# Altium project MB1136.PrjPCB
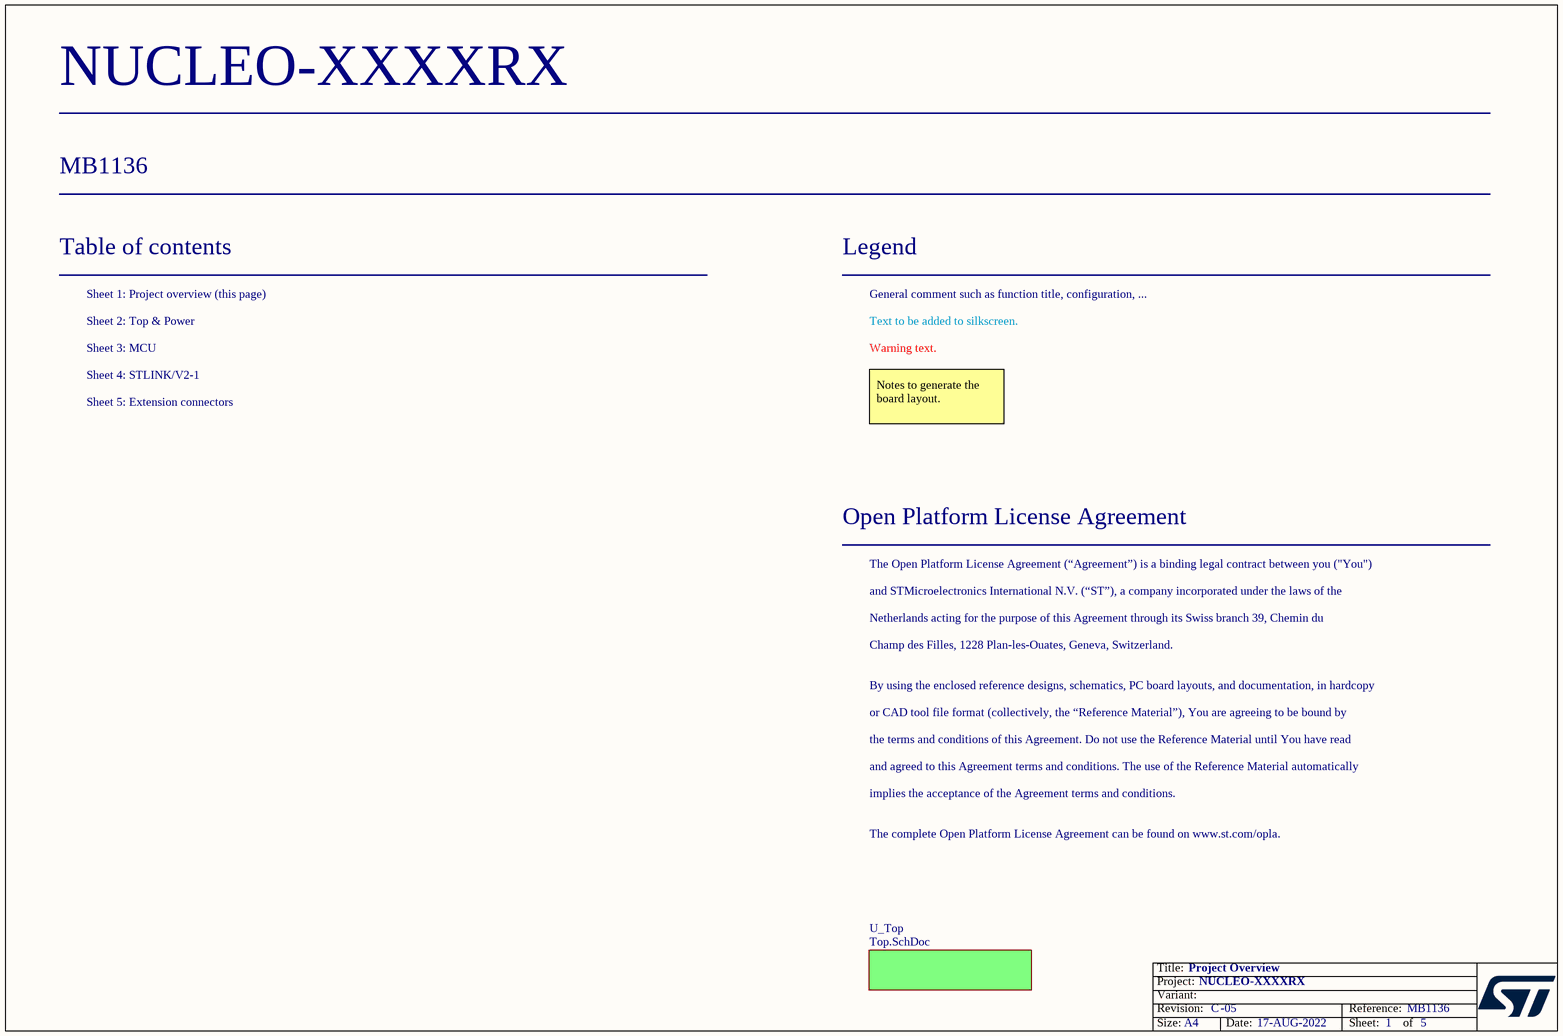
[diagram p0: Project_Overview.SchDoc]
Board_Reference: MB1136; Board_PCB_revision: C; Board_name: NUCLEO-XXXXRX; Board_Document_Date: 17-AUG-2022; Board_Assembly_revision: 05
5 sheets, 172 parts. Net scope: flat (ports and power ports of the same name join across sheets).
Sheets:
  Project_Overview.SchDoc
    U_Top = Top.SchDoc
      U_ST_LINK_V2-1 = ST_LINK_V2-1.SCHDOC
      U_Connectors = Connectors.SchDoc
      U_MCU_64 = MCU_64.SchDoc

## Sheet Project_Overview.SchDoc: Project Overview
size A4; Date: Not used; ApprovedBy: Not used; CheckedBy: Not used; Author: Not used; CompanyName: STMicroelectronics; DrawnBy: Not used; Engineer: Not used; Organization: Not used; Address1: Not used; Address2: Not used; Address3: Not used; Address4: Not used; DocumentNumber: MB1136; Revision: Not used; SheetNumber: 1; SheetTotal: 5

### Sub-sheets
U_Top = Top.SchDoc: no entries

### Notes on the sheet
- Table of contents
- Sheet 1: Project overview (this page)
- Legend
- General comment such as function title, configuration, ...
- Sheet 2: Top & Power
- Sheet 3: MCU
- Sheet 4: STLINK/V2-1
- Text to be added to silkscreen.
- Warning text.
- Sheet 5: Extension connectors
- Notes to generate the board layout.
- Open Platform License Agreement
- The Open Platform License Agreement (“Agreement”) is a binding legal contract between you ("You")
- and STMicroelectronics International N.V. (“ST”), a company incorporated under the laws of the
- Netherlands acting for the purpose of this Agreement through its Swiss branch 39, Chemin du
- Champ des Filles, 1228 Plan-les-Ouates, Geneva, Switzerland.
- By using the enclosed reference designs, schematics, PC board layouts, and documentation, in hardcopy
- or CAD tool file format (collectively, the “Reference Material”), You are agreeing to be bound by
- the terms and conditions of this Agreement. Do not use the Reference Material until You have read
- and agreed to this Agreement terms and conditions. The use of the Reference Material automatically
- implies the acceptance of the Agreement terms and conditions.
- The complete Open Platform License Agreement can be found on www.st.com/opla.

## Sheet Top.SchDoc: TOP & POWER
size A4; DocumentNumber: MB1136; Revision: C.3; SheetNumber: 2; SheetTotal: 5; Project: NUCLEO-XXXXRX
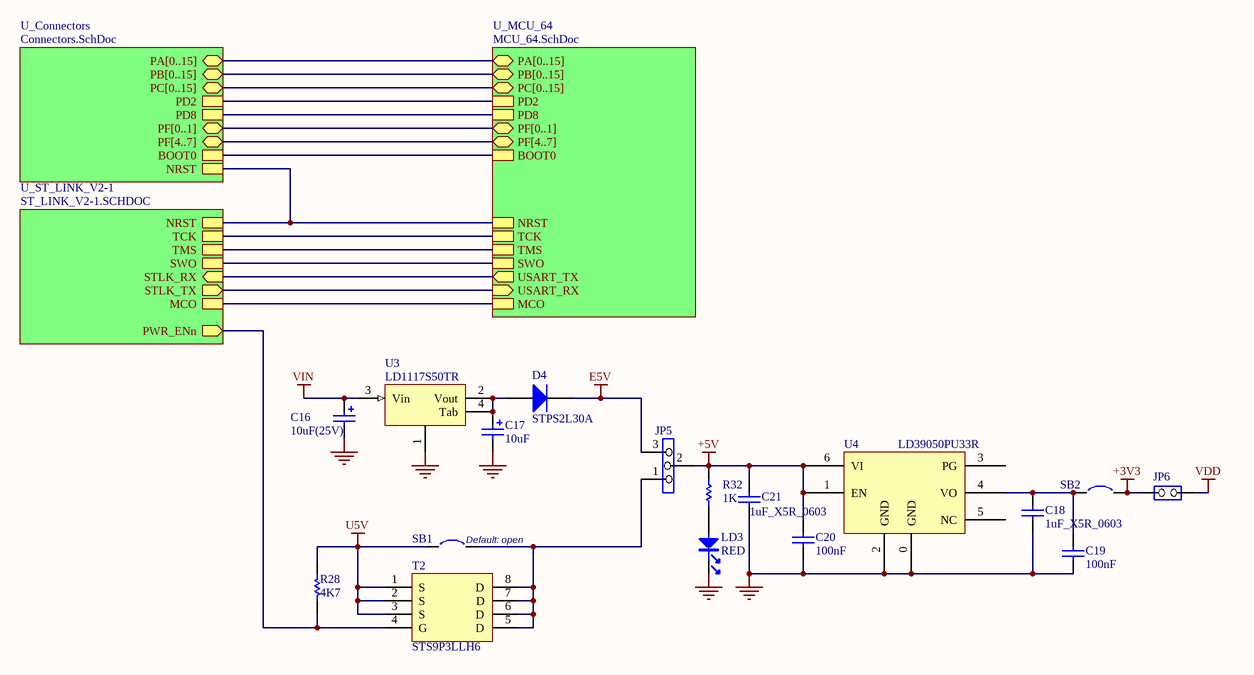
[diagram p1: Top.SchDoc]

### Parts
C16  10uF(25V)  [TAN-B]
C17  10uF  [TAN-A]
C18  1uF_X5R_0603  [0603C]
C19  100nF  [0603C]
C20  100nF  [0603C]
C21  1uF_X5R_0603  [0603C]
D4  STPS2L30A  [SMA]
JP5  (no value)  [SIP3]
JP6  (no value)  [SIP2/2.54]
LD3  RED  [0603D]
R28  4K7  [0603R]
R32  1K  [0603R]
SB1  Circuit Breaker  [JP2_SMD]  (value not drawn)
SB2  Circuit Breaker  [JP2_SMD]  (value not drawn)
T2  value STS9P3LLH6  [ICC_SO8_5X4_P127]  (hidden comment: TRANS_P-CHANNEL_STS9P3LLH6)
U3  LD1117S50TR  [SOT-223]
U4  LD39050PU33R  [DFN6(3X3)]

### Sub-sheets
U_Connectors = Connectors.SchDoc: PA[0..15] (bidir), PB[0..15] (bidir), PC[0..15] (bidir), PF[4..7] (bidir), PD2, PD8, PF[0..1] (bidir), NRST, BOOT0
U_MCU_64 = MCU_64.SchDoc: NRST, MCO, USART_RX (in), USART_TX (out), PA[0..15] (bidir), PB[0..15] (bidir), PC[0..15] (bidir), PF[4..7] (bidir), PD2, TCK, TMS, SWO, PD8, PF[0..1] (bidir), BOOT0
U_ST_LINK_V2-1 = ST_LINK_V2-1.SCHDOC: TMS, TCK, MCO, NRST, STLK_RX (in), STLK_TX (out), SWO, PWR_ENn (out)

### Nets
+3V3: JP6.1(COMMON) SB2.2
+5V: C20.2 C21.1 JP5.2 R32.2 U4.1(EN) U4.6(VI)
E5V: D4.2(K) JP5.3
GND: C16.2 C17.2 C18.2 C19.1 C20.1 C21.2 LD3.2 U3.1 U4.0(GND) U4.2(GND)
U5V: R28.1 SB1.1 T2.1(S) T2.2(S) T2.3(S)
VDD: JP6.2(NO)
VIN: C16.1 U3.3(Vin)
NetC17_1: C17.1 D4.1(A) U3.2(Vout) U3.4(Tab)
NetC18_1: C18.1 C19.2 SB2.1 U4.4(VO)
NetJP5_1: JP5.1 SB1.2 T2.5(D) T2.6(D) T2.7(D) T2.8(D)
NetLD3_1: LD3.1 R32.1
NetR28_2: R28.2 T2.4(G) ; sheet U_ST_LINK_V2-1/PWR_ENn
(unnamed): sheet U_ST_LINK_V2-1/TMS, sheet U_MCU_64/TMS
(unnamed): sheet U_ST_LINK_V2-1/TCK, sheet U_MCU_64/TCK  [a separate net that carries the same name]
(unnamed): sheet U_ST_LINK_V2-1/MCO, sheet U_MCU_64/MCO  [a separate net that carries the same name]
(unnamed): sheet U_ST_LINK_V2-1/NRST, sheet U_Connectors/NRST, sheet U_MCU_64/NRST  [a separate net that carries the same name]
(unnamed): sheet U_ST_LINK_V2-1/STLK_RX, sheet U_MCU_64/USART_TX  [a separate net that carries the same name]
(unnamed): sheet U_ST_LINK_V2-1/STLK_TX, sheet U_MCU_64/USART_RX  [a separate net that carries the same name]
(unnamed): sheet U_ST_LINK_V2-1/SWO, sheet U_MCU_64/SWO  [a separate net that carries the same name]
(unnamed): sheet U_Connectors/PD2, sheet U_MCU_64/PD2  [a separate net that carries the same name]
(unnamed): sheet U_Connectors/PD8, sheet U_MCU_64/PD8  [a separate net that carries the same name]
(unnamed): sheet U_Connectors/BOOT0, sheet U_MCU_64/BOOT0  [a separate net that carries the same name]

Not connected (* = marked no-connect by the designer): U4 3(PG) 5(NC)

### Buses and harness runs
bus sheet U_Connectors/PA[0..15] = sheet U_MCU_64/PA[0..15]
bus sheet U_Connectors/PB[0..15] = sheet U_MCU_64/PB[0..15]
bus sheet U_Connectors/PC[0..15] = sheet U_MCU_64/PC[0..15]
bus sheet U_Connectors/PF[0..1] = sheet U_MCU_64/PF[0..1]
bus sheet U_Connectors/PF[4..7] = sheet U_MCU_64/PF[4..7]

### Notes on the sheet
- (near SB1) Default: open

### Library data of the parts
C16 C17 = Cap Pol1: Polarized Capacitor (Radial)
C18 C21 = CAP SMD 0603  X5R 1µF 25V 10%: 0603  X5R 1µF; Rated voltage: 25V; Tolerance: 10%
C19 C20 = Capacitor_ST: Capacitor 0402 / 0603 / 0805
D4 = STPS2L30A: Manuf_1: STM; Provided: ST; Order: BAT60JFILM; ECCN_US/EU: EAR99/NEC
JP5 = Jumper3
JP6 = JP2
LD3 = PHOTO
R28 = Res1: Resistor; Value: 1K
R32 = Resistor_ST: Resistor 0402 / 0603 / 0805; Value: 10K
SB1 SB2 = Circuit Breaker: Solder: NO
T2 = MCD-02507: Transistor, MOSFET, P-CH, -30V, -9A, SO-8; Part_Preference: Recommended; Manufacturer: STMICROELECTRONICS; Component_Country_Of_Origin: China; ShowFields: YES; ID: 4613
U3 = LD1117
U4 = LD39050P

## Sheet ST_LINK_V2-1.SCHDOC: STLINK/V2-1
size A4; DocumentNumber: MB1136; Revision: C.3; SheetNumber: 4; SheetTotal: 5; Project: NUCLEO-XXXXRX
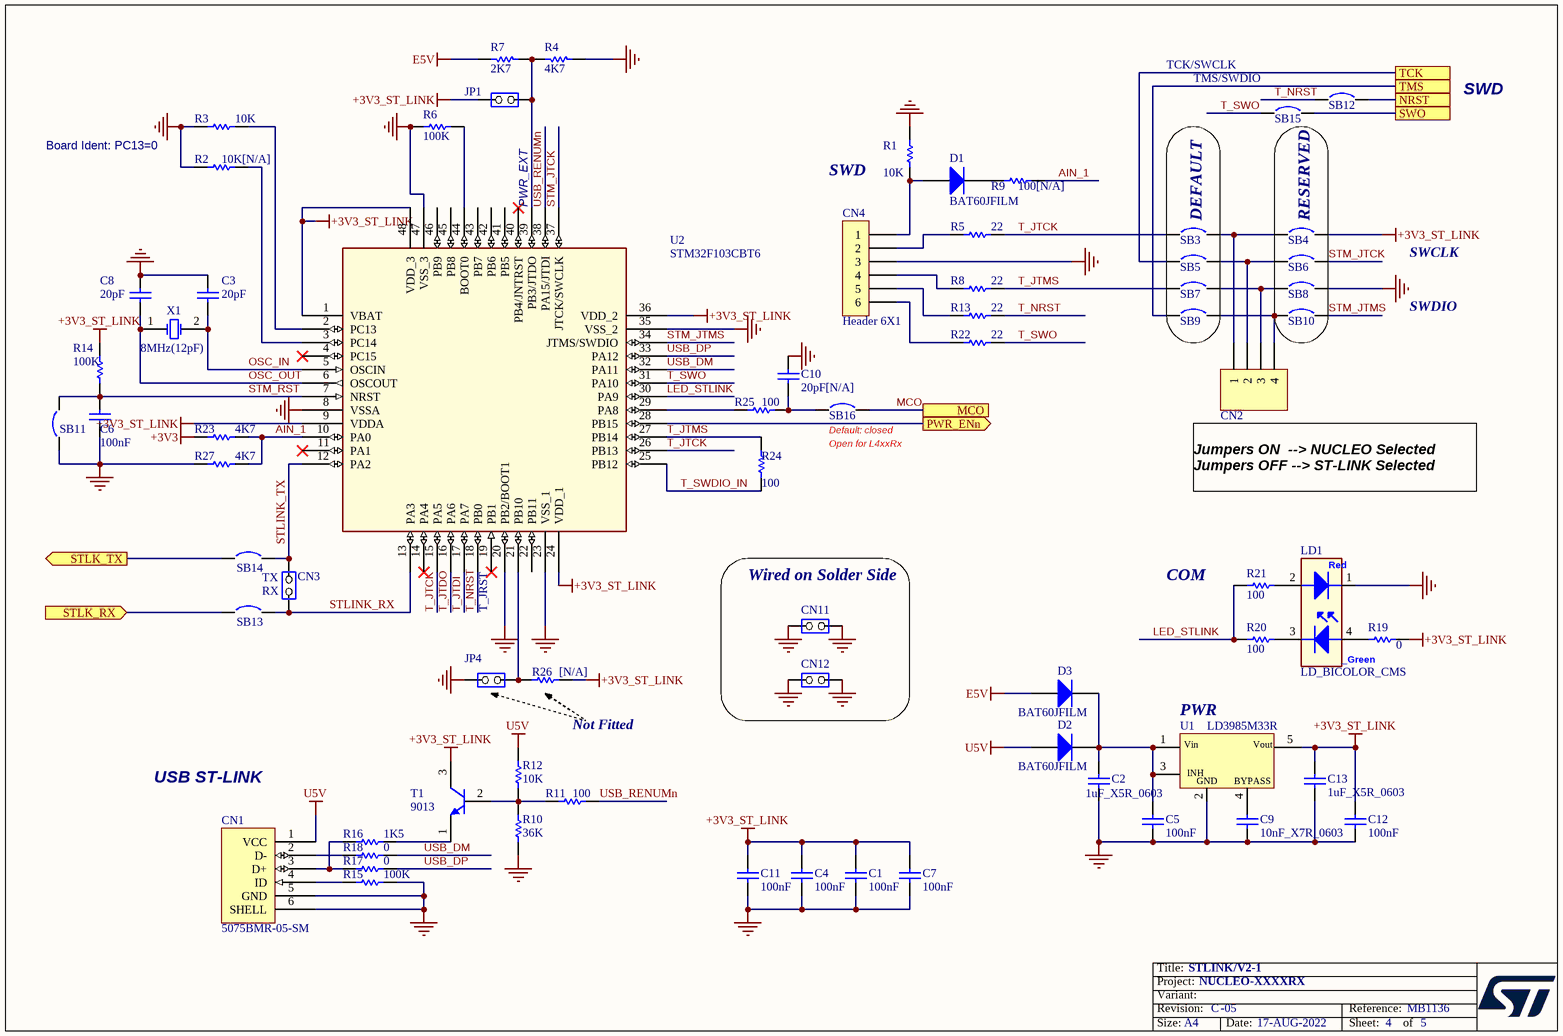
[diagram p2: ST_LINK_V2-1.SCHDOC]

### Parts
C1  100nF  [0603C]
C2  1uF_X5R_0603  [0603C]
C3  20pF  [0603C]
C4  100nF  [0603C]
C5  100nF  [0603C]
C6  100nF  [0603C]
C7  100nF  [0603C]
C8  20pF  [0603C]
C9  10nF_X7R_0603  [0603C]
C10  20pF[N/A]  [0603C]
C11  100nF  [0603C]
C12  100nF  [0603C]
C13  1uF_X5R_0603  [0603C]
CN1  5075BMR-05-SM  [USB-MINI-B-SMD]
CN2  Header 4  [1*4]  (value not drawn)
CN3  (no value)  [SIP2/2.54]
CN4  Header 6X1  [1*6P]
CN11  (no value)  [SIP2/2.54]
CN12  (no value)  [SIP2/2.54]
D1  BAT60JFILM  [SOD323/A]
D2  BAT60JFILM  [SOD323/A]
D3  BAT60JFILM  [SOD323/A]
JP1  (no value)  [SIP2/2.54]
JP4  (no value)  [SIP2/2.54]
LD1  LD_BICOLOR_CMS  [HSMF-A201]
R1  10K  [0603R]
R2  10K[N/A]  [0603R]
R3  10K  [0603R]
R4  4K7  [0603R]
R5  22  [0603R]
R6  100K  [0603R]
R7  2K7  [0603R]
R8  22  [0603R]
R9  100[N/A]  [0603R]
R10  36K  [0603R]
R11  100  [0603R]
R12  10K  [0603R]
R13  22  [0603R]
R14  100K  [0603R]
R15  100K  [0603R]
R16  1K5  [0603R]
R17  0  [0603R]
R18  0  [0603R]
R19  0  [0603R]
R20  100  [0603R]
R21  100  [0603R]
R22  22  [0603R]
R23  4K7  [0603R]
R24  100  [0603R]
R25  100  [0603R]
R26  [N/A]  [0603R]
R27  4K7  [0603R]
SB3  Circuit Breaker  [JP2_SMD]  (value not drawn)
SB4  Circuit Breaker  [JP2_SMD]  (value not drawn)
SB5  Circuit Breaker  [JP2_SMD]  (value not drawn)
SB6  Circuit Breaker  [JP2_SMD]  (value not drawn)
SB7  Circuit Breaker  [JP2_SMD]  (value not drawn)
SB8  Circuit Breaker  [JP2_SMD]  (value not drawn)
SB9  Circuit Breaker  [JP2_SMD]  (value not drawn)
SB10  Circuit Breaker  [JP2_SMD]  (value not drawn)
SB11  Circuit Breaker  [JP2_SMD]  (value not drawn)
SB12  Circuit Breaker  [JP2_SMD]  (value not drawn)
SB13  Circuit Breaker  [JP2_SMD]  (value not drawn)
SB14  Circuit Breaker  [JP2_SMD]  (value not drawn)
SB15  Circuit Breaker  [JP2_SMD]  (value not drawn)
SB16  Circuit Breaker  [JP2_SMD]  (value not drawn)
T1  9013  [SOT-23]
U1  LD3985M33R  [SOT-23-5L]
U2  STM32F103CBT6  [QFP48 7X7]
X1  8MHz(12pF)  [XTAL1]

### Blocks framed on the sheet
DEFAULT: SB3 SB5 SB7 SB9
RESERVED: SB4 SB6 SB8 SB10
Wired on Solder Side: CN11 CN12

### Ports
MCO, NRST, PWR_ENn (out), STLK_RX (in), STLK_TX (out), SWO, TCK, TMS

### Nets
+3V3: R23.1
+3V3_ST_LINK: C1.2 C4.2 C7.2 C11.2 C12.2 C13.1 JP1.1(COMMON) R14.2 R19.2 R26.1 SB4.2 T1.3(C) U1.5(Vout) U2.1(VBAT) U2.9(VDDA) U2.24(VDD_1) U2.36(VDD_2) U2.48(VDD_3)
E5V: D3.1(A) R7.1
GND: C1.1 C2.1 C3.2 C4.1 C5.1 C6.1 C7.1 C8.2 C9.1 C10.2 C11.1 C12.1 C13.2 CN1.5(GND) CN1.6(SHELL) CN4.3 CN11.1(COMMON) CN11.2(NO) CN12.1(COMMON) CN12.2(NO) JP4.1(COMMON) LD1.1 R1.2 R2.1 R3.1 R4.2 R6.1 R10.1 R15.2 R27.1 SB8.2 SB11.1 U1.2(GND) U2.8(VSSA) U2.20(PB2/BOOT1) U2.23(VSS_1) U2.35(VSS_2) U2.47(VSS_3)
U5V: CN1.1(VCC) D2.1(A) R12.2
AIN_1: R9.2 R23.2 R27.2 U2.10(PA0)
LED_STLINK: R20.1 R21.1 U2.30(PA9)
MCO: SB16.2 ; port MCO
NRST: SB12.2 ; port NRST
OSC_IN: C3.1 U2.5(OSCIN) X1.2(OSC2)
OSC_OUT: C8.1 U2.6(OSCOUT) X1.1(OSC1)
PA13: SB9.1 ; port TMS
PA14: SB5.1 ; port TCK
PB3: SB15.2 ; port SWO
STLINK_RX: CN3.1(COMMON) SB13.2 U2.13(PA3)
STLINK_TX: CN3.2(NO) SB14.2 U2.12(PA2)
STM_JTCK: SB6.2 U2.37(JTCK/SWCLK)
STM_JTMS: SB10.2 U2.34(JTMS/SWDIO)
STM_RST: C6.2 R14.1 SB11.2 U2.7(NRST)
T_JTCK: R5.2 SB3.1 U2.15(PA5) U2.26(PB13)
T_JTDI: U2.17(PA7)
T_JTDO: U2.16(PA6)
T_JTMS: R8.2 R24.2 SB7.1 U2.27(PB14)
T_NRST: R13.2 SB12.1 U2.18(PB0)
T_SWDIO_IN: R24.1 U2.25(PB12)
T_SWO: R22.2 SB15.1 U2.31(PA10)
USB_DM: R18.2 U2.32(PA11)
USB_DP: R17.2 U2.33(PA12)
USB_RENUMn: R11.2 U2.38(PA15/JTDI)
NetC2_2: C2.2 C5.2 D2.2(K) D3.2(K) U1.1(Vin) U1.3(CE)
NetC9_2: C9.2 U1.4(BYPASS)
NetC10_1: C10.1 R25.2 SB16.1
NetCN1_2: CN1.2(D-) R18.1
NetCN1_3: CN1.3(D+) R16.1 R17.1
NetCN1_4: CN1.4(ID) R15.1
NetCN2_1: CN2.1 SB3.2 SB4.1
NetCN2_2: CN2.2 SB5.2 SB6.1
NetCN2_3: CN2.3 SB7.2 SB8.1
NetCN2_4: CN2.4 SB9.2 SB10.1
NetCN4_1: CN4.1 D1.1(A) R1.1
NetCN4_2: CN4.2 R5.1
NetCN4_4: CN4.4 R8.1
NetCN4_5: CN4.5 R13.1
NetCN4_6: CN4.6 R22.1
NetD1_2: D1.2(K) R9.1
NetJP1_2: JP1.2(NO) R4.1 R7.2 U2.39(PB3/JTDO)
NetJP4_2: JP4.2(NO) R26.2 U2.21(PB10)
NetLD1_2: LD1.2 R21.2
NetLD1_3: LD1.3 R20.2
NetLD1_4: LD1.4 R19.1
NetR2_2: R2.2 U2.3(PC14)
NetR3_2: R3.2 U2.2(PC13)
NetR6_2: R6.2 U2.44(BOOT0)
NetR10_2: R10.2 R11.1 R12.1 T1.2(B)
NetR16_2: R16.2 T1.1(E)
NetR25_1: R25.1 U2.29(PA8)
NetSB13_1: SB13.1 ; port STLK_RX
NetSB14_1: SB14.1 ; port STLK_TX
NetU2_28: U2.28(PB15) ; port PWR_ENn

Not connected (* = marked no-connect by the designer): U2 4(PC15)* 11(PA1)* 14(PA4)* 19(PB1)* 22(PB11) 40(PB4/JNTRST)* 41(PB5) 42(PB6) 43(PB7) 45(PB8) 46(PB9)

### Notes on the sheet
- TCK/SWCLK
- (near SB15) TMS/SWDIO
- SWD
- Board Ident: PC13=0
- (near U2) PWR_EXT
- SWCLK
- SWDIO
- (near SB16) Default: closed
- (near SB16) Open for L4xxRx
- Jumpers ON  --> NUCLEO Selected
  Jumpers OFF --> ST-LINK Selected
- TX
- COM
- RX
- T_JRST
- (near U1) PWR
- USB ST-LINK
- Not Fitted

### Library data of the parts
C1 C4-C7 C11 C12 = Capacitor_ST: Capacitor 0402 / 0603 / 0805
C2 C13 = CAP SMD 0603  X5R 1µF 25V 10%: as C18 on sheet Top
C3 C8 C10 = Capacitor_ST: Capacitor 0402 / 0603 / 0805; Value: 100nF
C9 = CAP SMD 0603  X7R 10000PF 50V 10%: 0603  X7R 10NF; Order code RS: 2040779; Rated voltage: 50V; Tolerance: 10%
CN1 = USB-MINI-typeB connector
CN2 = Header 4: Header, 4-Pin, Single row
CN3 = JP2: Fitted: NO
CN4 = Header 6X1: Header, 6-Pin, Single row
CN11 CN12 JP1 JP4 = JP2
D1-D3 = BAT60JFILM: Manuf_1: STM; Provided: ST; ECCN_US/EU: EAR99/NEC
LD1 = LD_BICOLOR_CMS: Bicolor Led; Manuf_Part_1: HSMF-A201-A00J1; Manuf_1: Avago Technologies; Ref St: xxxxxx; cap_dec: ----
R1 R3 = Resistor_ST: Resistor 0402 / 0603 / 0805
R2 R23 R27 = Resistor_ST: Resistor 0402 / 0603 / 0805; Value: 10K; Fitted: NO
R4 R7 R10 R12 R26 = Res1: Resistor; Value: 1K
R5 R6 R8 R9 R11 R13-R22 R24 R25 = Resistor_ST: Resistor 0402 / 0603 / 0805; Value: 10K
SB3 SB5 SB7 SB9 SB11 SB13-SB16 = Circuit Breaker: Solder: NO
SB4 SB6 SB8 SB10 SB12 = Circuit Breaker: Solder: YES
T1 = NPN: NPN Bipolar Transistor; Code - JEDEC: TO-226-AA
U1 = LD3985M33R: Ultra low drop-low noise BiCMOS voltage, regulators low ESR capacitors compatible; Manuf_1: STM; Provided: ST; Ref St: 9176161; ECCN_US/EU: EAR99/NEC
U2 = STM32F103CBT6: Medium-density performance line ARM-based 32-bit MCU with 64KB Flash; Manuf_Part_1: STM32F103C8T6; Manuf_1: STM; Ref St: 9175981; Provided: ST; ECCN_US/EU: 3A991A2/NEC
X1 = XTAL: Crystal Oscillator

## Sheet Connectors.SchDoc: Extension connectors
size A4; DocumentNumber: MB1136; Revision: C.3; SheetNumber: 5; SheetTotal: 5; Project: NUCLEO-XXXXRX
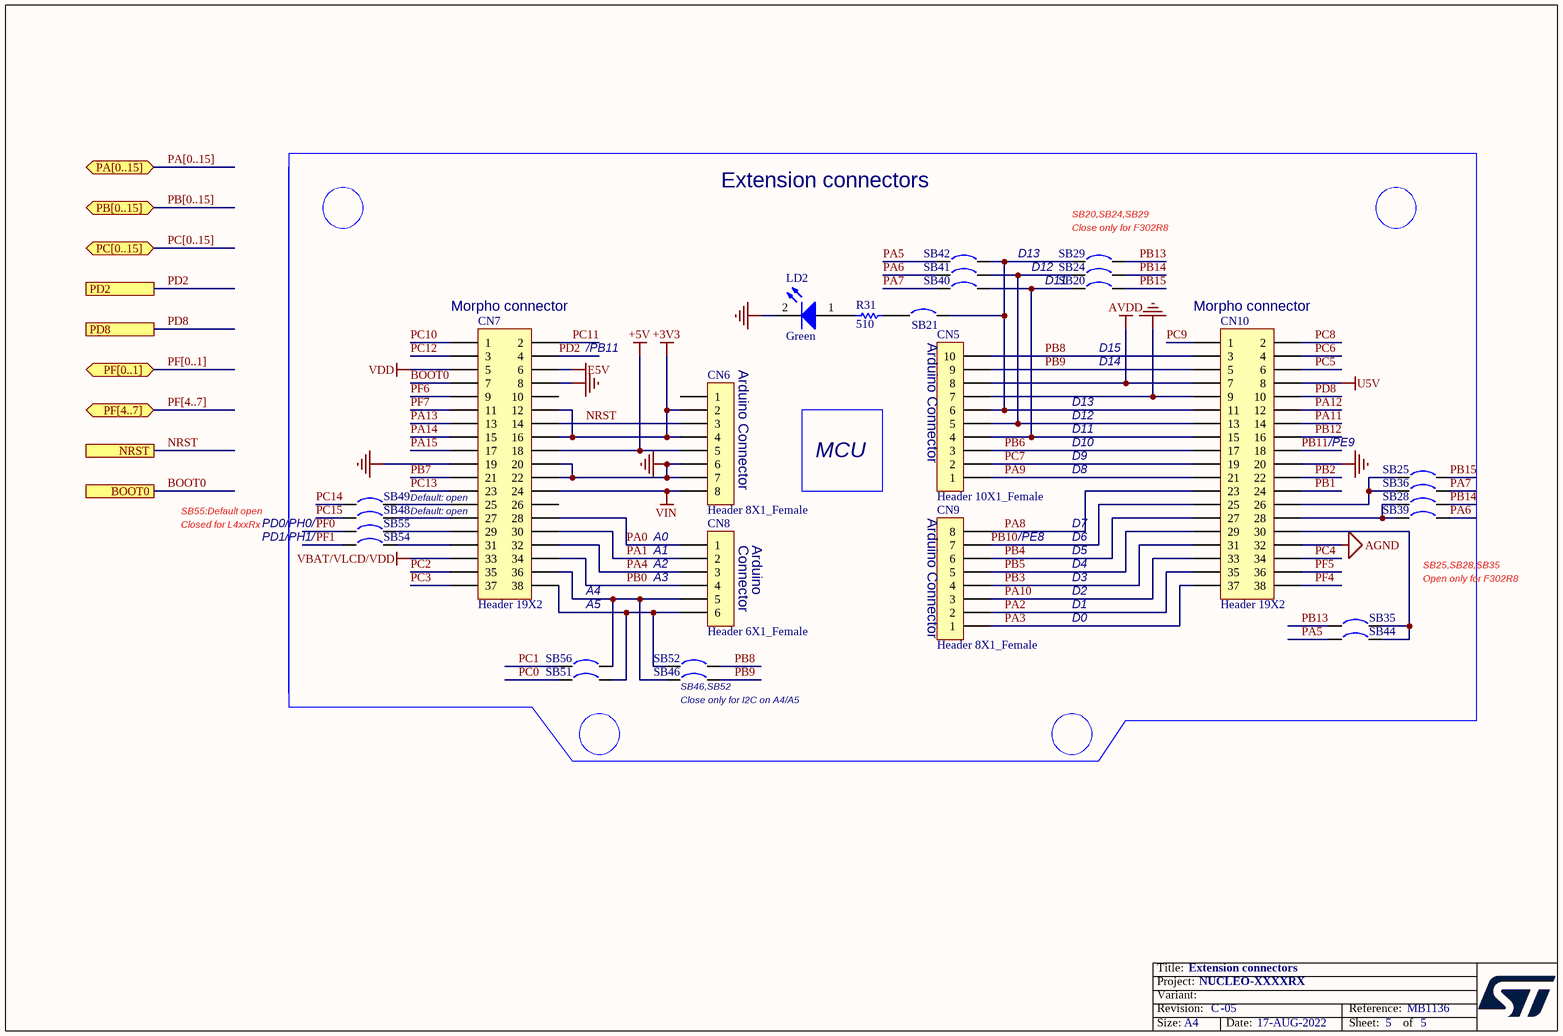
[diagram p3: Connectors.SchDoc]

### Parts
CN5  Header 10X1_Female  [1*10P_FEMALE]
CN6  Header 8X1_Female  [1*8P_FEMALE]
CN7  Header 19X2  [2*19P]
CN8  Header 6X1_Female  [1*6P_FEMALE]
CN9  Header 8X1_Female  [1*8P_FEMALE]
CN10  Header 19X2  [2*19P]
LD2  Green  [0603D]
R31  510  [0603R]
SB20  Circuit Breaker  [JP2_SMD]  (value not drawn)
SB21  Circuit Breaker  [JP2_SMD]  (value not drawn)
SB24  Circuit Breaker  [JP2_SMD]  (value not drawn)
SB25  Circuit Breaker  [JP2_SMD]  (value not drawn)
SB28  Circuit Breaker  [JP2_SMD]  (value not drawn)
SB29  Circuit Breaker  [JP2_SMD]  (value not drawn)
SB35  Circuit Breaker  [JP2_SMD]  (value not drawn)
SB36  Circuit Breaker  [JP2_SMD]  (value not drawn)
SB39  Circuit Breaker  [JP2_SMD]  (value not drawn)
SB40  Circuit Breaker  [JP2_SMD]  (value not drawn)
SB41  Circuit Breaker  [JP2_SMD]  (value not drawn)
SB42  Circuit Breaker  [JP2_SMD]  (value not drawn)
SB44  Circuit Breaker  [JP2_SMD]  (value not drawn)
SB46  Circuit Breaker  [JP2_SMD]  (value not drawn)
SB48  Circuit Breaker  [JP2_SMD]  (value not drawn)
SB49  Circuit Breaker  [JP2_SMD]  (value not drawn)
SB51  Circuit Breaker  [JP2_SMD]  (value not drawn)
SB52  Circuit Breaker  [JP2_SMD]  (value not drawn)
SB54  Circuit Breaker  [JP2_SMD]  (value not drawn)
SB55  Circuit Breaker  [JP2_SMD]  (value not drawn)
SB56  Circuit Breaker  [JP2_SMD]  (value not drawn)

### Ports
BOOT0, NRST, PA[0..15] (bidir), PB[0..15] (bidir), PC[0..15] (bidir), PD2, PD8, PF[0..1] (bidir), PF[4..7] (bidir)

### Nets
+3V3: CN6.2 CN6.4 CN7.12 CN7.16
+5V: CN6.5 CN7.18
AGND: CN10.32
AVDD: CN5.8 CN10.7
E5V: CN7.6
GND: CN5.7 CN6.6 CN6.7 CN7.8 CN7.19 CN7.20 CN7.22 CN10.9 CN10.20 LD2.2(K)
U5V: CN10.8
VBAT/VLCD/VDD: CN7.33
VDD: CN7.5
VIN: CN6.8 CN7.24
BOOT0: CN7.7 ; port BOOT0
NRST: CN6.3 CN7.14 ; port NRST
PA0: CN7.28 CN8.1
PA1: CN7.30 CN8.2
PA2: CN9.2 CN10.35
PA3: CN9.1 CN10.37
PA4: CN7.32 CN8.3
PA5: SB42.1 SB44.2
PA6: SB39.1 SB41.1
PA7: SB36.1 SB40.1
PA8: CN9.8 CN10.23
PA9: CN5.1 CN10.21
PA10: CN9.3 CN10.33
PA11: CN10.14
PA12: CN10.12
PA13: CN7.13
PA14: CN7.15
PA15: CN7.17
PB0: CN7.34 CN8.4
PB1: CN10.24
PB2: CN10.22
PB3: CN9.4 CN10.31
PB4: CN9.6 CN10.27
PB5: CN9.5 CN10.29
PB6: CN5.3 CN10.17
PB7: CN7.21
PB8: CN5.10 CN10.3 SB52.2
PB9: CN5.9 CN10.5 SB46.2
PB10: CN9.7 CN10.25
PB11: CN10.18
PB12: CN10.16
PB13: SB29.2 SB35.2
PB14: SB24.2 SB28.1
PB15: SB20.2 SB25.1
PC0: SB51.1
PC1: SB56.1
PC2: CN7.35
PC3: CN7.37
PC4: CN10.34
PC5: CN10.6
PC6: CN10.4
PC7: CN5.2 CN10.19
PC8: CN10.2
PC9: CN10.1
PC10: CN7.1
PC11: CN7.2
PC12: CN7.3
PC13: CN7.23
PC14: SB49.2
PC15: SB48.2
PD2: CN7.4 ; port PD2
PD8: CN10.10 ; port PD8
PF0: SB55.2
PF1: SB54.2
PF4: CN10.38
PF5: CN10.36
PF6: CN7.9
PF7: CN7.11
NetCN5_4: CN5.4 CN10.15 SB20.1 SB40.2
NetCN5_5: CN5.5 CN10.13 SB24.1 SB41.2
NetCN5_6: CN5.6 CN10.11 SB21.2 SB29.1 SB42.2
NetCN7_25: CN7.25 SB49.1
NetCN7_27: CN7.27 SB48.1
NetCN7_29: CN7.29 SB55.1
NetCN7_31: CN7.31 SB54.1
NetCN7_36: CN7.36 CN8.5 SB46.1 SB56.2
NetCN7_38: CN7.38 CN8.6 SB51.2 SB52.1
NetCN10_26: CN10.26 SB25.2 SB36.2
NetCN10_28: CN10.28 SB28.2 SB39.2
NetCN10_30: CN10.30 SB35.1 SB44.1
NetLD2_1: LD2.1(A) R31.2
NetR31_1: R31.1 SB21.1

Not connected (* = marked no-connect by the designer): CN6 1; CN7 10 26

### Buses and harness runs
bus PA[0..15] = port PA[0..15]
bus PB[0..15] = port PB[0..15]
bus PC[0..15] = port PC[0..15]
bus PF[0..1] = port PF[0..1]
bus PF[4..7] = port PF[4..7]

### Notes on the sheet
- Extension connectors
- Close only for F302R8
- SB20,SB24,SB29
- (near CN7) Morpho connector
- D13
- D12
- D11
- (near CN10) Morpho connector
- /PB11
- (near CN6) Arduino Connector
- Arduino Connector
- D14
- D15
- D10
- /PE9
- SB55:Default open
- (near CN7) Default: open
- MCU
- (near CN9) Arduino Connector
- D8
- D9
- Closed for L4xxRx
- PD0/PH0/
- PD1/PH1/
- A0
- (near CN8) A1
- (near CN8) A2
- (near CN8) A3
- (near CN8) Connector
- (near CN8) Arduino
- /PE8
- D4
- D3
- D5
- D6
- D7
- Open only for F302R8
- SB25,SB28,SB35
- A4
- A5
- D0
- D1
- D2
- (near SB46) Close only for I2C on A4/A5
- (near SB46) SB46,SB52

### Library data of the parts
CN5 = Header 10X1_Female: Header, 10-Pin, Single row,female
CN6 CN9 = Header 8X1_Female: Header, 8-Pin, Single row,female
CN7 CN10 = Header 19X2: Header, 19-Pin, Dual row
CN8 = Header 6X1_Female: Header, 6-Pin, Single row,female
LD2 = LED2: Typical RED, GREEN, YELLOW, AMBER GaAs LED
R31 = Res1: Resistor; Value: 1K
SB20 SB21 SB24 SB25 SB28 SB29 SB35 SB36 SB39-SB42 SB44 SB46 SB48 SB49 SB51 SB52 SB54-SB56 = Circuit Breaker: Solder: NO

## Sheet MCU_64.SchDoc: MCU
size A4; DocumentNumber: MB1136; Revision: C.3; SheetNumber: 3; SheetTotal: 5; Project: NUCLEO-XXXXRX
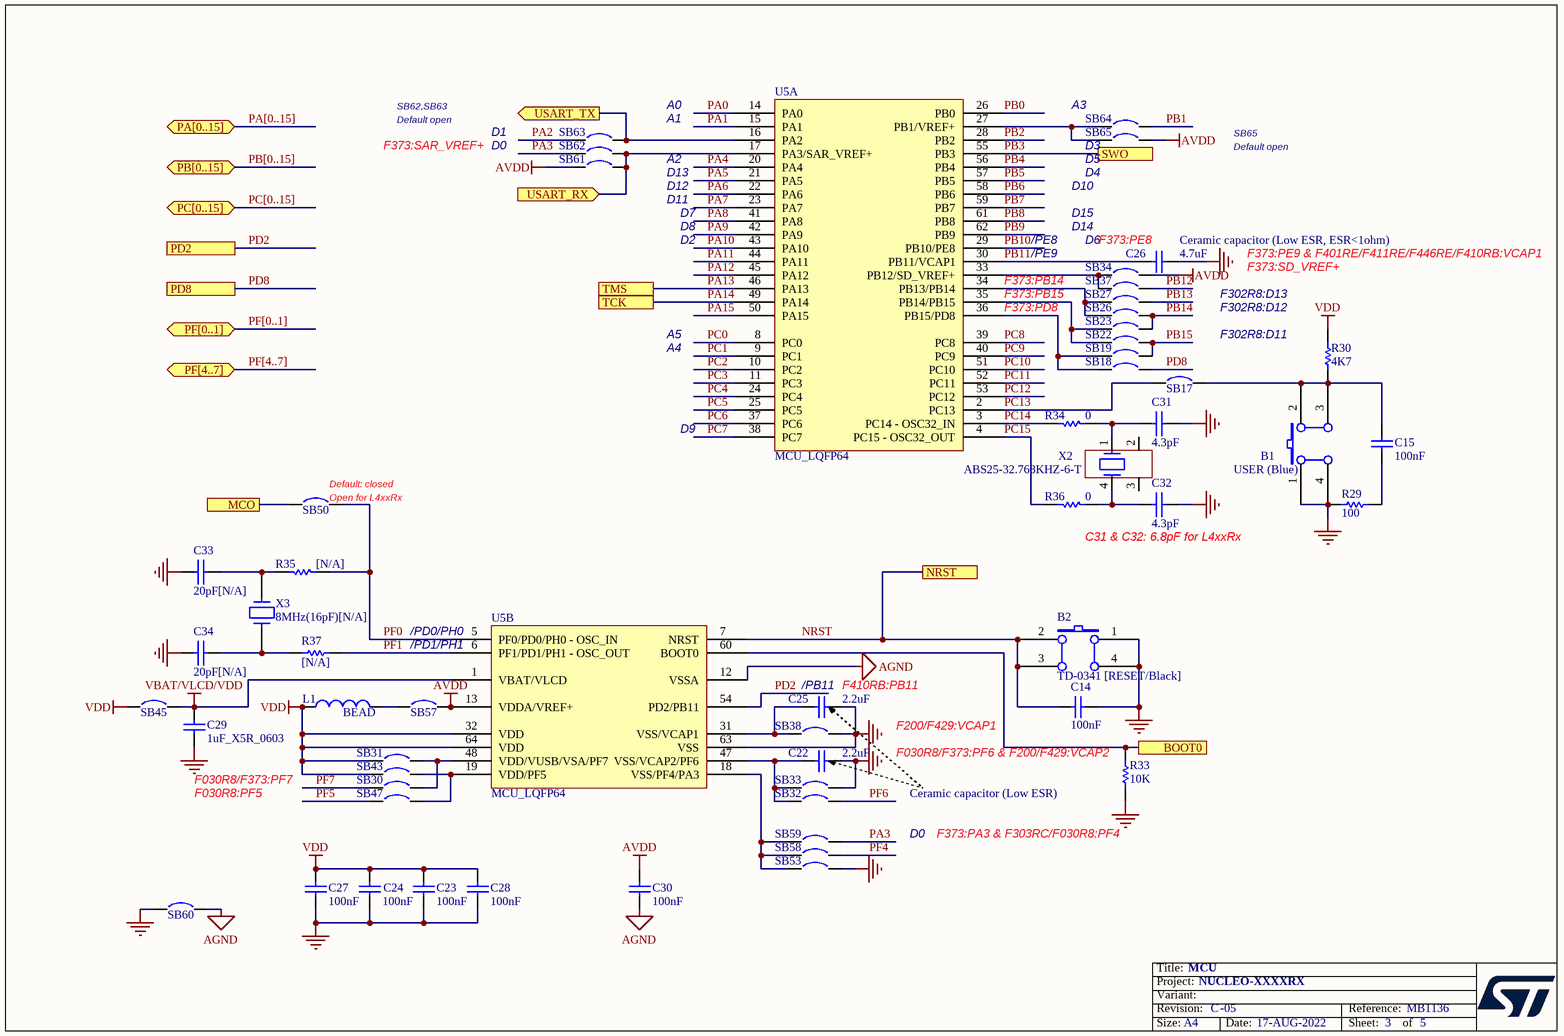
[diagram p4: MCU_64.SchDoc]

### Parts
B1  USER (Blue)  [PB10]
B2  TD-0341 [RESET/Black]  [PB10]
C14  100nF  [0603C]
C15  100nF  [0603C]
C22  2.2uF  [TAN-A]
C23  100nF  [0603C]
C24  100nF  [0603C]
C25  2.2uF  [TAN-A]
C26  4.7uF  [TAN-A]
C27  100nF  [0603C]
C28  100nF  [0603C]
C29  1uF_X5R_0603  [0603C]
C30  100nF  [0603C]
C31  4.3pF  [0603C]
C32  4.3pF  [0603C]
C33  20pF[N/A]  [0603C]
C34  20pF[N/A]  [0603C]
L1  BEAD  [0603L]
R29  100  [0603R]
R30  4K7  [0603R]
R33  10K  [0603R]
R34  0  [0603R]
R35  [N/A]  [0603R]
R36  0  [0603R]
R37  [N/A]  [0603R]
SB17  Circuit Breaker  [JP2_SMD]  (value not drawn)
SB18  Circuit Breaker  [JP2_SMD]  (value not drawn)
SB19  Circuit Breaker  [JP2_SMD]  (value not drawn)
SB22  Circuit Breaker  [JP2_SMD]  (value not drawn)
SB23  Circuit Breaker  [JP2_SMD]  (value not drawn)
SB26  Circuit Breaker  [JP2_SMD]  (value not drawn)
SB27  Circuit Breaker  [JP2_SMD]  (value not drawn)
SB30  Circuit Breaker  [JP2_SMD]  (value not drawn)
SB31  Circuit Breaker  [JP2_SMD]  (value not drawn)
SB32  Circuit Breaker  [JP2_SMD]  (value not drawn)
SB33  Circuit Breaker  [JP2_SMD]  (value not drawn)
SB34  Circuit Breaker  [JP2_SMD]  (value not drawn)
SB37  Circuit Breaker  [JP2_SMD]  (value not drawn)
SB38  Circuit Breaker  [JP2_SMD]  (value not drawn)
SB43  Circuit Breaker  [JP2_SMD]  (value not drawn)
SB45  Circuit Breaker  [JP2_SMD]  (value not drawn)
SB47  Circuit Breaker  [JP2_SMD]  (value not drawn)
SB50  Circuit Breaker  [JP2_SMD]  (value not drawn)
SB53  Circuit Breaker  [JP2_SMD]  (value not drawn)
SB57  Circuit Breaker  [JP2_SMD]  (value not drawn)
SB58  Circuit Breaker  [JP2_SMD]  (value not drawn)
SB59  Circuit Breaker  [JP2_SMD]  (value not drawn)
SB60  Circuit Breaker  [JP2_SMD]  (value not drawn)
SB61  Circuit Breaker  [JP2_SMD]  (value not drawn)
SB62  Circuit Breaker  [JP2_SMD]  (value not drawn)
SB63  Circuit Breaker  [JP2_SMD]  (value not drawn)
SB64  Circuit Breaker  [JP2_SMD]  (value not drawn)
SB65  Circuit Breaker  [JP2_SMD]  (value not drawn)
U5  MCU_LQFP64  [LQFP64]  (parts A,B of 2)
X2  ABS25-32.768KHZ-6-T  [XTAL_4SM_8X3R8]
X3  8MHz(16pF)[N/A]  [XTAL1]

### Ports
BOOT0, MCO, NRST, PA[0..15] (bidir), PB[0..15] (bidir), PC[0..15] (bidir), PD2, PD8, PF[0..1] (bidir), PF[4..7] (bidir), SWO, TCK, TMS, USART_RX (in), USART_TX (out)

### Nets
AGND: C30.2 SB60.2 U5.12(VSSA)
AVDD: C30.1 SB34.2 SB57.2 SB61.1 SB65.2 U5.13(VDDA/VREF+)
GND: B1.1(A0) B1.4(A1) B2.1(A0) B2.4(A1) C14.1 C22.2 C23.2 C24.2 C25.2 C26.2 C27.2 C28.2 C29.2 C31.2 C32.2 C33.2 C34.2 R29.1 R33.2 SB33.2 SB38.2 SB53.2 SB60.1 U5.63(VSS)
VBAT/VLCD/VDD: C29.1 SB45.2 U5.1(VBAT/VLCD)
VDD: C23.1 C24.1 C27.1 C28.1 L1.1 R30.2 SB31.1 SB43.1 SB45.1 U5.32(VDD) U5.64(VDD)
BOOT0: R33.1 U5.60(BOOT0) ; port BOOT0
MCO: SB50.1 ; port MCO
NRST: B2.2(B0) B2.3(B1) C14.2 U5.7(NRST) ; port NRST
PA0: U5.14(PA0)
PA1: U5.15(PA1)
PA2: SB63.1
PA3: SB59.2 SB62.1
PA4: U5.20(PA4)
PA5: U5.21(PA5)
PA6: U5.22(PA6)
PA7: U5.23(PA7)
PA8: U5.41(PA8)
PA9: U5.42(PA9)
PA10: U5.43(PA10)
PA11: U5.44(PA11)
PA12: U5.45(PA12)
PA13: U5.46(PA13) ; port TMS
PA14: U5.49(PA14) ; port TCK
PA15: U5.50(PA15)
PB0: U5.26(PB0)
PB1: SB64.2
PB2: U5.28(PB2)
PB3: U5.55(PB3) ; port SWO
PB4: U5.56(PB4)
PB5: U5.57(PB5)
PB6: U5.58(PB6)
PB7: U5.59(PB7)
PB8: U5.61(PB8)
PB9: U5.62(PB9)
PB10: U5.29(PB10/PE8)
PB11: C26.1 U5.30(PB11/VCAP1)
PB12: SB37.2
PB13: SB27.2
PB14: SB23.2 SB26.2
PB15: SB19.2 SB22.2
PC0: U5.8(PC0)
PC1: U5.9(PC1)
PC2: U5.10(PC2)
PC3: U5.11(PC3)
PC4: U5.24(PC4)
PC5: U5.25(PC5)
PC6: U5.37(PC6)
PC7: U5.38(PC7)
PC8: U5.39(PC8)
PC9: U5.40(PC9)
PC10: U5.51(PC10)
PC11: U5.52(PC11)
PC12: U5.53(PC12)
PC13: SB17.1 U5.2(PC13)
PC14: R34.2 U5.3(PC14_-_OSC32_IN)
PC15: R36.2 U5.4(PC15_-_OSC32_OUT)
PD2: U5.54(PD2/PB11) ; port PD2
PD8: SB18.2 ; port PD8
PF0: R35.1 SB50.2 U5.5(PF0/PD0/PH0_-_OSC_IN)
PF1: R37.1 U5.6(PF1/PD1/PH1_-_OSC_OUT)
PF4: SB58.2
PF5: SB47.1
PF6: SB32.2
PF7: SB30.1
NetB1_2: B1.2(B0) B1.3(B1) C15.2 R30.1 SB17.2
NetC15_1: C15.1 R29.2
NetC22_1: C22.1 SB32.1 SB33.1 U5.47(VSS/VCAP2/PF6)
NetC25_1: C25.1 SB38.1 U5.31(VSS/VCAP1)
NetC31_1: C31.1 R34.1 X2.1
NetC32_1: C32.1 R36.1 X2.4
NetC33_1: C33.1 R35.2 X3.2
NetC34_1: C34.1 R37.2 X3.1
NetL1_2: L1.2 SB57.1
NetSB18_1: SB18.1 SB19.1 U5.36(PB15/PD8)
NetSB22_1: SB22.1 SB23.1 U5.35(PB14/PB15)
NetSB26_1: SB26.1 SB27.1 U5.34(PB13/PB14)
NetSB30_2: SB30.2 SB31.2 U5.48(VDD/VUSB/VSA/PF7)
NetSB34_1: SB34.1 SB37.1 U5.33(PB12/SD_VREF+)
NetSB43_2: SB43.2 SB47.2 U5.19(VDD/PF5)
NetSB53_1: SB53.1 SB58.1 SB59.1 U5.18(VSS/PF4/PA3)
NetSB61_2: SB61.2 SB62.2 U5.17(PA3/SAR_VREF+) ; port USART_RX
NetSB63_2: SB63.2 U5.16(PA2) ; port USART_TX
NetSB64_1: SB64.1 SB65.1 U5.27(PB1/VREF+)

Not connected (* = marked no-connect by the designer): X2 2 3

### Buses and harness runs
bus PA[0..15] = port PA[0..15]
bus PB[0..15] = port PB[0..15]
bus PC[0..15] = port PC[0..15]
bus PF[0..1] = port PF[0..1]
bus PF[4..7] = port PF[4..7]

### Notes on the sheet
- SB62,SB63
- A0
- A3
- F373:SAR_VREF+
- Default open
- D0
- D1
- A1
- A2
- D13
- D4
- D3
- D5
- SB65
- D12
- D11
- D2
- D7
- D8
- /PE8
- D14
- D15
- D10
- D6
- (near C26) F373:PE8
- (near C26) Ceramic capacitor (Low ESR, ESR<1ohm)
- F373:PB14
- F373:PB15
- F373:PD8
- /PE9
- F302R8:D12
- F302R8:D13
- F373:PE9 & F401RE/F411RE/F446RE/F410RB:VCAP1
- F373:SD_VREF+
- A4
- A5
- F302R8:D11
- D9
- (near SB50) Default: closed
- (near SB50) Open for L4xxRx
- C31 & C32: 6.8pF for L4xxRx
- (near U5) /PD0/PH0
- (near U5) /PD1/PH1
- (near C25) /PB11
- (near C25) F410RB:PB11
- (near C29) F030R8/F373:PF7
- F200/F429:VCAP1
- F030R8/F373:PF6 & F200/F429:VCAP2
- F030R8:PF5
- Ceramic capacitor (Low ESR)
- (near R33) F373:PA3 & F303RC/F030R8:PF4

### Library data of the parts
B1 B2 = SW PUSHBUTTON: SE PUSHBUTTON
C14 C15 = CAP: Capacitor; Value: 100pF
C22 C25 = Cap_2.2uF_X7R_10%_0805: Capacitor,2.2uF,16V, X7R,10%,0805,YAGEO; Manuf_Part_1: CC0805KKX7R7BB225
C23 C24 C27 C28 C30 = Cap: Capacitor; Value: 10nF
C26 = Cap_2.2uF_X7R_10%_0805: Capacitor,4.7uF,25V, X7R,10%,1206,YAGEO; Manuf_Part_1: CC0805KKX7R7BB225; Value: 2.2uF
C29 = CAP SMD 0603  X5R 1µF 25V 10%: as C18 on sheet Top
C31-C34 = CAP: Capacitor
L1 = Inductor: Value: 100uH
R29 R34-R37 = Res1: Resistor; Value: 1K
R30 R33 = res1: Resistor; Value: 1K
SB17-SB19 SB22 SB23 SB26 SB27 SB30-SB34 SB37 SB38 SB43 SB45 SB47 SB50 SB53 SB57-SB65 = Circuit Breaker: Solder: NO
X2 = MC306
X3 = CRYSTAL

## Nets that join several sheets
+3V3: Top (JP6.1 SB2.2), ST_LINK_V2-1 (R23.1), Connectors (CN6.2 CN6.4 CN7.12 CN7.16)
+5V: Top (6 pins), Connectors (CN6.5 CN7.18)
AGND: Connectors (CN10.32), MCU_64 (C30.2 SB60.2 U5.12)
AVDD: Connectors (CN5.8 CN10.7), MCU_64 (6 pins)
E5V: Top (D4.2 JP5.3), ST_LINK_V2-1 (D3.1 R7.1), Connectors (CN7.6)
GND: Top (10 pins), ST_LINK_V2-1 (38 pins), Connectors (10 pins), MCU_64 (24 pins)
U5V: Top (5 pins), ST_LINK_V2-1 (CN1.1 D2.1 R12.2), Connectors (CN10.8)
VBAT/VLCD/VDD: Connectors (CN7.33), MCU_64 (C29.1 SB45.2 U5.1)
VDD: Top (JP6.2), Connectors (CN7.5), MCU_64 (11 pins)
VIN: Top (C16.1 U3.3), Connectors (CN6.8 CN7.24)
BOOT0: Connectors (CN7.7), MCU_64 (R33.1 U5.60)
MCO: ST_LINK_V2-1 (SB16.2), MCU_64 (SB50.1)
NRST: ST_LINK_V2-1 (SB12.2), Connectors (CN6.3 CN7.14), MCU_64 (B2.2 B2.3 C14.2 U5.7)
PA0: Connectors (CN7.28 CN8.1), MCU_64 (U5.14)
PA1: Connectors (CN7.30 CN8.2), MCU_64 (U5.15)
PA2: Connectors (CN9.2 CN10.35), MCU_64 (SB63.1)
PA3: Connectors (CN9.1 CN10.37), MCU_64 (SB59.2 SB62.1)
PA4: Connectors (CN7.32 CN8.3), MCU_64 (U5.20)
PA5: Connectors (SB42.1 SB44.2), MCU_64 (U5.21)
PA6: Connectors (SB39.1 SB41.1), MCU_64 (U5.22)
PA7: Connectors (SB36.1 SB40.1), MCU_64 (U5.23)
PA8: Connectors (CN9.8 CN10.23), MCU_64 (U5.41)
PA9: Connectors (CN5.1 CN10.21), MCU_64 (U5.42)
PA10: Connectors (CN9.3 CN10.33), MCU_64 (U5.43)
PA11: Connectors (CN10.14), MCU_64 (U5.44)
PA12: Connectors (CN10.12), MCU_64 (U5.45)
PA13: ST_LINK_V2-1 (SB9.1), Connectors (CN7.13), MCU_64 (U5.46)
PA14: ST_LINK_V2-1 (SB5.1), Connectors (CN7.15), MCU_64 (U5.49)
PA15: Connectors (CN7.17), MCU_64 (U5.50)
PB0: Connectors (CN7.34 CN8.4), MCU_64 (U5.26)
PB1: Connectors (CN10.24), MCU_64 (SB64.2)
PB2: Connectors (CN10.22), MCU_64 (U5.28)
PB3: ST_LINK_V2-1 (SB15.2), Connectors (CN9.4 CN10.31), MCU_64 (U5.55)
PB4: Connectors (CN9.6 CN10.27), MCU_64 (U5.56)
PB5: Connectors (CN9.5 CN10.29), MCU_64 (U5.57)
PB6: Connectors (CN5.3 CN10.17), MCU_64 (U5.58)
PB7: Connectors (CN7.21), MCU_64 (U5.59)
PB8: Connectors (CN5.10 CN10.3 SB52.2), MCU_64 (U5.61)
PB9: Connectors (CN5.9 CN10.5 SB46.2), MCU_64 (U5.62)
PB10: Connectors (CN9.7 CN10.25), MCU_64 (U5.29)
PB11: Connectors (CN10.18), MCU_64 (C26.1 U5.30)
PB12: Connectors (CN10.16), MCU_64 (SB37.2)
PB13: Connectors (SB29.2 SB35.2), MCU_64 (SB27.2)
PB14: Connectors (SB24.2 SB28.1), MCU_64 (SB23.2 SB26.2)
PB15: Connectors (SB20.2 SB25.1), MCU_64 (SB19.2 SB22.2)
PC0: Connectors (SB51.1), MCU_64 (U5.8)
PC1: Connectors (SB56.1), MCU_64 (U5.9)
PC2: Connectors (CN7.35), MCU_64 (U5.10)
PC3: Connectors (CN7.37), MCU_64 (U5.11)
PC4: Connectors (CN10.34), MCU_64 (U5.24)
PC5: Connectors (CN10.6), MCU_64 (U5.25)
PC6: Connectors (CN10.4), MCU_64 (U5.37)
PC7: Connectors (CN5.2 CN10.19), MCU_64 (U5.38)
PC8: Connectors (CN10.2), MCU_64 (U5.39)
PC9: Connectors (CN10.1), MCU_64 (U5.40)
PC10: Connectors (CN7.1), MCU_64 (U5.51)
PC11: Connectors (CN7.2), MCU_64 (U5.52)
PC12: Connectors (CN7.3), MCU_64 (U5.53)
PC13: Connectors (CN7.23), MCU_64 (SB17.1 U5.2)
PC14: Connectors (SB49.2), MCU_64 (R34.2 U5.3)
PC15: Connectors (SB48.2), MCU_64 (R36.2 U5.4)
PD2: Connectors (CN7.4), MCU_64 (U5.54)
PD8: Connectors (CN10.10), MCU_64 (SB18.2)
PF0: Connectors (SB55.2), MCU_64 (R35.1 SB50.2 U5.5)
PF1: Connectors (SB54.2), MCU_64 (R37.1 U5.6)
PF4: Connectors (CN10.38), MCU_64 (SB58.2)
PF5: Connectors (CN10.36), MCU_64 (SB47.1)
PF6: Connectors (CN7.9), MCU_64 (SB32.2)
PF7: Connectors (CN7.11), MCU_64 (SB30.1)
